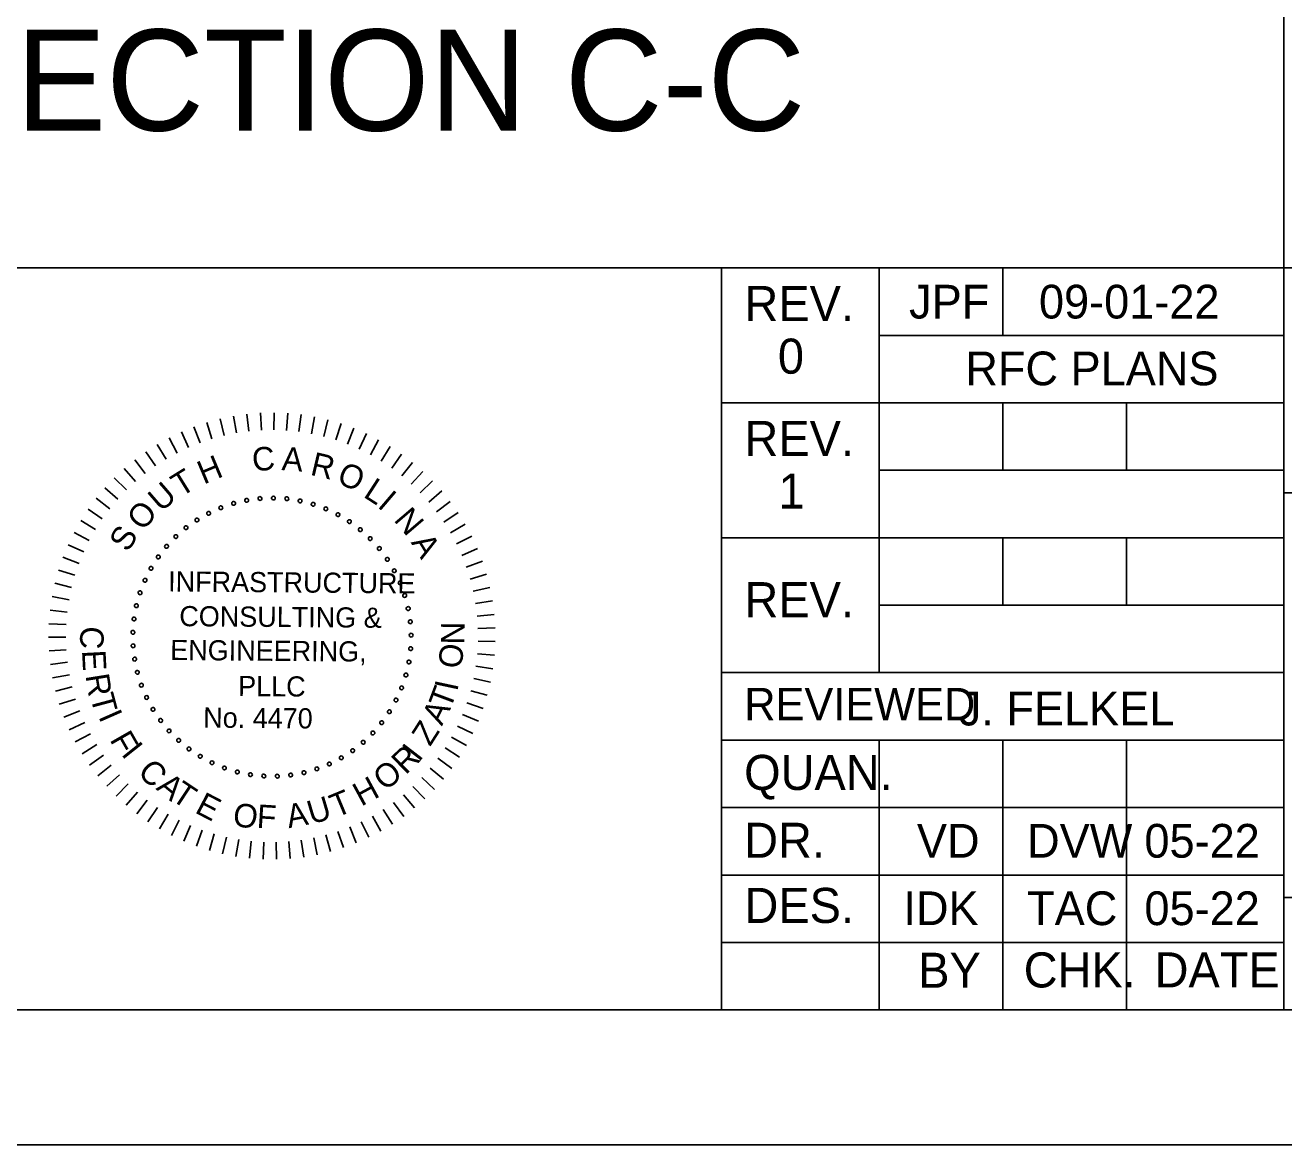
# Model space of a CAD drawing. Extents: x 1970675.2 to 1970711.3, y 796145.2 to 796167.2.
# Drawn here: x 1970700.655 to 1970705.319, y 796145.246 to 796149.396 of the extents above; entities that cross this region are included whole.
import ezdxf

# ---------------------------------------------------------------- set-up
doc = ezdxf.new("R2010")
doc.units = 0
for name, color, linetype in [('BR_BORDER LINES', 7, 'Continuous'), ('BR_TEXT', 7, 'Continuous'), ('Level 31', 7, 'Continuous')]:
    doc.layers.add(name, color=color, linetype=linetype)

msp = doc.modelspace()

# ---------------------------------------------------------------- linework, layer by layer
at = {"layer": 'BR_BORDER LINES'}
for p, q in [((1970705.3189, 796145.7463), (1970705.3189, 796151.0229)), ((1970697.8703, 796148.4964), (1970703.2355, 796148.4964)), ((1970703.2355, 796145.7463), (1970703.2355, 796148.4964)), ((1970703.2355, 796148.4964), (1970710.7358, 796148.4964)), ((1970703.8189, 796148.4964), (1970703.8189, 796146.9963)), ((1970704.2772, 796148.2464), (1970704.2772, 796148.4964)), ((1970703.8189, 796148.2464), (1970705.3189, 796148.2464)), ((1970703.2355, 796147.9964), (1970705.3189, 796147.9964)), ((1970704.2772, 796147.7464), (1970704.2772, 796147.9964)), ((1970704.7356, 796147.7464), (1970704.7356, 796147.9964)), ((1970703.8189, 796147.7464), (1970705.3189, 796147.7464)), ((1970705.3189, 796147.663), (1970705.3189, 796147.663)), ((1970705.3189, 796147.663), (1970710.736, 796147.663)), ((1970703.2355, 796147.4964), (1970705.3189, 796147.4964)), ((1970704.2772, 796147.2463), (1970704.2772, 796147.4964)), ((1970704.7356, 796147.2463), (1970704.7356, 796147.4964)), ((1970703.8189, 796147.2463), (1970705.3189, 796147.2463)), ((1970703.2355, 796146.9963), (1970705.3189, 796146.9963)), ((1970703.2355, 796146.7463), (1970705.3189, 796146.7463)), ((1970703.8189, 796146.7463), (1970703.8189, 796145.7463)), ((1970704.2772, 796146.7463), (1970704.2772, 796145.7463)), ((1970704.7356, 796146.7463), (1970704.7356, 796145.7463)), ((1970703.2355, 796146.4963), (1970705.3189, 796146.4963)), ((1970703.2355, 796146.2463), (1970705.3189, 796146.2463)), ((1970705.3189, 796146.163), (1970710.7358, 796146.163)), ((1970703.2355, 796145.9963), (1970705.3189, 796145.9963)), ((1970677.0698, 796145.7463), (1970710.7358, 796145.7463))]:
    msp.add_line(p, q, dxfattribs=at)
at = {"layer": 'BR_TEXT'}
for p, q in [((1970701.3767, 796147.9371), (1970701.3916, 796147.8752)), ((1970701.4262, 796147.9473), (1970701.4372, 796147.8846)), ((1970701.4761, 796147.9545), (1970701.4834, 796147.8913)), ((1970701.5265, 796147.9587), (1970701.5298, 796147.8951)), ((1970701.5769, 796147.9597), (1970701.5764, 796147.8961)), ((1970701.6274, 796147.9577), (1970701.623, 796147.8942)), ((1970701.6776, 796147.9526), (1970701.6693, 796147.8895)), ((1970701.7274, 796147.9445), (1970701.7153, 796147.882)), ((1970701.7767, 796147.9333), (1970701.7608, 796147.8717)), ((1970701.2334, 796147.8887), (1970701.2593, 796147.8305)), ((1970701.2802, 796147.9077), (1970701.3025, 796147.8481)), ((1970701.328, 796147.9239), (1970701.3466, 796147.863)), ((1970701.8251, 796147.9192), (1970701.8055, 796147.8586)), ((1970701.8726, 796147.9021), (1970701.8494, 796147.8428)), ((1970701.1439, 796147.8422), (1970701.1766, 796147.7876)), ((1970701.1879, 796147.8668), (1970701.2173, 796147.8103)), ((1970701.919, 796147.8822), (1970701.8922, 796147.8244)), ((1970701.9641, 796147.8594), (1970701.9338, 796147.8034)), ((1970701.1014, 796147.8149), (1970701.1374, 796147.7625)), ((1970702.0077, 796147.834), (1970701.974, 796147.78)), ((1970702.0497, 796147.8059), (1970702.0128, 796147.7541)), ((1970701.0217, 796147.7529), (1970701.0639, 796147.7052)), ((1970701.0606, 796147.7852), (1970701.0998, 796147.735)), ((1970702.0899, 796147.7754), (1970702.0499, 796147.7259)), ((1970700.9849, 796147.7184), (1970701.0299, 796147.6734)), ((1970702.1281, 796147.7424), (1970702.0852, 796147.6954)), ((1970702.1643, 796147.7072), (1970702.1186, 796147.6629)), ((1970700.9502, 796147.6817), (1970700.9979, 796147.6395)), ((1970702.1982, 796147.6699), (1970702.1499, 796147.6284)), ((1970700.9179, 796147.643), (1970700.968, 796147.6037)), ((1970702.2299, 796147.6305), (1970702.1791, 796147.5921)), ((1970700.8605, 796147.5599), (1970700.9151, 796147.5271)), ((1970700.8879, 796147.6023), (1970700.9404, 796147.5662)), ((1970702.259, 796147.5893), (1970702.206, 796147.5541)), ((1970700.8358, 796147.5159), (1970700.8922, 796147.4865)), ((1970702.2856, 796147.5464), (1970702.2305, 796147.5145)), ((1970700.8137, 796147.4705), (1970700.8719, 796147.4445)), ((1970702.3095, 796147.5019), (1970702.2526, 796147.4734)), ((1970700.7945, 796147.4238), (1970700.8541, 796147.4014)), ((1970702.3307, 796147.4561), (1970702.2722, 796147.4311)), ((1970700.7782, 796147.3761), (1970700.839, 796147.3574)), ((1970702.3491, 796147.4091), (1970702.2891, 796147.3877)), ((1970700.7648, 796147.3274), (1970700.8267, 796147.3124)), ((1970702.3645, 796147.361), (1970702.3033, 796147.3433)), ((1970702.377, 796147.3121), (1970702.3148, 796147.2982)), ((1970700.7543, 796147.278), (1970700.817, 796147.2668)), ((1970702.3864, 796147.2625), (1970702.3236, 796147.2524)), ((1970700.747, 796147.228), (1970700.8102, 796147.2207)), ((1970702.3929, 796147.2124), (1970702.3295, 796147.2062)), ((1970700.7426, 796147.1777), (1970700.8062, 796147.1743)), ((1970702.3963, 796147.1621), (1970702.3326, 796147.1597)), ((1970700.7414, 796147.1273), (1970700.8051, 796147.1277)), ((1970702.3965, 796147.1116), (1970702.3329, 796147.1131)), ((1970700.7432, 796147.0768), (1970700.8067, 796147.0812)), ((1970702.3938, 796147.0612), (1970702.3303, 796147.0666)), ((1970700.7481, 796147.0266), (1970700.8113, 796147.0348)), ((1970702.3879, 796147.011), (1970702.3249, 796147.0203)), ((1970700.7561, 796146.9767), (1970700.8186, 796146.9888)), ((1970702.379, 796146.9613), (1970702.3167, 796146.9744)), ((1970700.7671, 796146.9275), (1970700.8287, 796146.9433)), ((1970702.3671, 796146.9123), (1970702.3057, 796146.9291)), ((1970700.781, 796146.8789), (1970700.8416, 796146.8985)), ((1970702.3522, 796146.864), (1970702.2919, 796146.8846)), ((1970700.7979, 796146.8314), (1970700.8572, 796146.8546)), ((1970702.3344, 796146.8168), (1970702.2755, 796146.841)), ((1970700.8177, 796146.7849), (1970700.8755, 796146.8117)), ((1970700.8403, 796146.7397), (1970700.8963, 796146.77)), ((1970702.3138, 796146.7707), (1970702.2564, 796146.7985)), ((1970700.8655, 796146.696), (1970700.9196, 796146.7297)), ((1970702.2904, 796146.726), (1970702.2348, 796146.7572)), ((1970700.8934, 796146.654), (1970700.9453, 796146.6908)), ((1970702.2356, 796146.6412), (1970702.1843, 796146.6789)), ((1970702.2643, 796146.6828), (1970702.2107, 796146.7173)), ((1970700.9238, 796146.6137), (1970700.9734, 796146.6536)), ((1970702.2044, 796146.6015), (1970702.1555, 796146.6423)), ((1970700.9566, 796146.5753), (1970701.0037, 796146.6182)), ((1970700.9917, 796146.539), (1970701.0361, 796146.5847)), ((1970702.1709, 796146.5638), (1970702.1245, 796146.6074)), ((1970701.0289, 796146.5049), (1970701.0704, 796146.5532)), ((1970702.0973, 796146.4948), (1970702.0566, 796146.5437)), ((1970702.1351, 796146.5281), (1970702.0915, 796146.5745)), ((1970701.0682, 796146.4731), (1970701.1066, 796146.5239)), ((1970701.1093, 796146.4438), (1970701.1446, 796146.4968)), ((1970702.0158, 796146.4352), (1970701.9813, 796146.4888)), ((1970702.0574, 796146.4637), (1970702.0198, 796146.5151)), ((1970701.1521, 796146.4171), (1970701.1841, 796146.4721)), ((1970701.1965, 796146.393), (1970701.225, 796146.4499)), ((1970701.9276, 796146.386), (1970701.9, 796146.4434)), ((1970701.9725, 796146.4093), (1970701.9414, 796146.4648)), ((1970701.2422, 796146.3716), (1970701.2673, 796146.4302)), ((1970701.2892, 796146.3531), (1970701.3106, 796146.4131)), ((1970701.3372, 796146.3375), (1970701.3549, 796146.3986)), ((1970701.7859, 796146.3332), (1970701.7691, 796146.3947)), ((1970701.8342, 796146.3479), (1970701.8137, 796146.4082)), ((1970701.8815, 796146.3656), (1970701.8574, 796146.4245)), ((1970701.386, 796146.3248), (1970701.4001, 796146.3869)), ((1970701.4356, 796146.3152), (1970701.4458, 796146.378)), ((1970701.4856, 796146.3086), (1970701.492, 796146.3719)), ((1970701.536, 796146.305), (1970701.5385, 796146.3686)), ((1970701.5865, 796146.3045), (1970701.5851, 796146.3682)), ((1970701.6369, 796146.3071), (1970701.6316, 796146.3706)), ((1970701.6871, 796146.3128), (1970701.6779, 796146.3758)), ((1970701.7368, 796146.3215), (1970701.7238, 796146.3838))]:
    msp.add_line(p, q, dxfattribs=at)
for centre, start, end in [((1970701.3797, 796147.6075), 21.6807, 201.6807), ((1970701.3797, 796147.6075), 201.6807, 21.6807), ((1970701.4268, 796147.6235), 16.1422, 196.1422), ((1970701.4268, 796147.6235), 196.1422, 16.1422), ((1970701.4753, 796147.635), 10.6038, 190.6038), ((1970701.4753, 796147.635), 190.6038, 10.6038), ((1970701.5247, 796147.6417), 5.0653, 185.0653), ((1970701.5247, 796147.6417), 185.0653, 5.0653), ((1970701.5745, 796147.6436), 359.5268, 179.5268), ((1970701.5745, 796147.6436), 179.5268, 359.5268), ((1970701.6242, 796147.6407), 173.9884, 353.9884), ((1970701.6242, 796147.6407), 353.9884, 173.9884), ((1970701.6735, 796147.6329), 168.4499, 348.4499), ((1970701.6735, 796147.6329), 348.4499, 168.4499), ((1970701.7217, 796147.6205), 162.9114, 342.9114), ((1970701.7217, 796147.6205), 342.9114, 162.9114), ((1970701.7686, 796147.6035), 157.373, 337.373), ((1970701.7686, 796147.6035), 337.373, 157.373), ((1970701.291, 796147.5621), 32.7576, 212.7576), ((1970701.291, 796147.5621), 212.7576, 32.7576), ((1970701.3343, 796147.587), 27.2191, 207.2191), ((1970701.3343, 796147.587), 207.2191, 27.2191), ((1970701.8135, 796147.582), 151.8345, 331.8345), ((1970701.8135, 796147.582), 331.8345, 151.8345), ((1970701.8562, 796147.5563), 146.2961, 326.2961), ((1970701.8562, 796147.5563), 326.2961, 146.2961), ((1970701.2504, 796147.5333), 38.2961, 218.2961), ((1970701.2504, 796147.5333), 218.2961, 38.2961), ((1970701.8962, 796147.5266), 140.7576, 320.7576), ((1970701.8962, 796147.5266), 320.7576, 140.7576), ((1970701.1785, 796147.4645), 49.373, 229.373), ((1970701.1785, 796147.4645), 229.373, 49.373), ((1970701.2128, 796147.5006), 43.8345, 223.8345), ((1970701.2128, 796147.5006), 223.8345, 43.8345), ((1970701.9332, 796147.4932), 135.2191, 315.2191), ((1970701.9332, 796147.4932), 315.2191, 135.2191), ((1970701.1478, 796147.4252), 54.9114, 234.9114), ((1970701.1478, 796147.4252), 234.9114, 54.9114), ((1970701.9668, 796147.4564), 129.6807, 309.6807), ((1970701.9668, 796147.4564), 309.6807, 129.6807), ((1970701.9966, 796147.4165), 124.1422, 304.1422), ((1970701.9966, 796147.4165), 304.1422, 124.1422), ((1970701.1211, 796147.3831), 60.4499, 240.4499), ((1970701.1211, 796147.3831), 240.4499, 60.4499), ((1970702.0225, 796147.3739), 118.6038, 298.6038), ((1970702.0225, 796147.3739), 298.6038, 118.6038), ((1970701.0986, 796147.3387), 65.9884, 245.9884), ((1970701.0986, 796147.3387), 245.9884, 65.9884), ((1970702.0441, 796147.329), 113.0653, 293.0653), ((1970702.0441, 796147.329), 293.0653, 113.0653), ((1970701.0804, 796147.2923), 71.5268, 251.5268), ((1970701.0804, 796147.2923), 251.5268, 71.5268), ((1970702.0613, 796147.2822), 107.5268, 287.5268), ((1970702.0613, 796147.2822), 287.5268, 107.5268), ((1970701.0668, 796147.2443), 77.0653, 257.0653), ((1970701.0668, 796147.2443), 257.0653, 77.0653), ((1970702.0739, 796147.234), 101.9884, 281.9884), ((1970702.0739, 796147.234), 281.9884, 101.9884), ((1970701.0579, 796147.1953), 82.6038, 262.6038), ((1970701.0579, 796147.1953), 262.6038, 82.6038), ((1970702.0818, 796147.1848), 96.4499, 276.4499), ((1970702.0818, 796147.1848), 276.4499, 96.4499), ((1970701.0538, 796147.1456), 88.1422, 268.1422), ((1970701.0538, 796147.1456), 268.1422, 88.1422), ((1970702.0849, 796147.1351), 90.9114, 270.9114), ((1970702.0849, 796147.1351), 270.9114, 90.9114), ((1970701.0545, 796147.0958), 93.6807, 273.6807), ((1970701.0545, 796147.0958), 273.6807, 93.6807), ((1970701.06, 796147.0463), 99.2191, 279.2191), ((1970701.06, 796147.0463), 279.2191, 99.2191), ((1970702.0832, 796147.0853), 85.373, 265.373), ((1970702.0832, 796147.0853), 265.373, 85.373), ((1970701.0703, 796146.9975), 104.7576, 284.7576), ((1970701.0703, 796146.9975), 284.7576, 104.7576), ((1970702.0766, 796147.0359), 79.8345, 259.8345), ((1970702.0766, 796147.0359), 259.8345, 79.8345), ((1970701.0852, 796146.95), 110.2961, 290.2961), ((1970701.0852, 796146.95), 290.2961, 110.2961), ((1970702.0654, 796146.9873), 74.2961, 254.2961), ((1970702.0654, 796146.9873), 254.2961, 74.2961), ((1970701.1046, 796146.9041), 115.8345, 295.8345), ((1970701.1046, 796146.9041), 295.8345, 115.8345), ((1970702.0495, 796146.9401), 68.7576, 248.7576), ((1970702.0495, 796146.9401), 248.7576, 68.7576), ((1970701.1284, 796146.8603), 121.373, 301.373), ((1970701.1284, 796146.8603), 301.373, 121.373), ((1970702.0291, 796146.8946), 63.2191, 243.2191), ((1970702.0291, 796146.8946), 243.2191, 63.2191), ((1970701.1563, 796146.819), 126.9114, 306.9114), ((1970701.1563, 796146.819), 306.9114, 126.9114), ((1970701.9758, 796146.8106), 52.1422, 232.1422), ((1970701.9758, 796146.8106), 232.1422, 52.1422), ((1970702.0045, 796146.8513), 57.6807, 237.6807), ((1970702.0045, 796146.8513), 237.6807, 57.6807), ((1970701.188, 796146.7806), 132.4499, 312.4499), ((1970701.188, 796146.7806), 312.4499, 132.4499), ((1970701.9432, 796146.7728), 46.6038, 226.6038), ((1970701.9432, 796146.7728), 226.6038, 46.6038), ((1970701.2233, 796146.7454), 137.9884, 317.9884), ((1970701.2233, 796146.7454), 317.9884, 137.9884), ((1970701.2618, 796146.7138), 323.5268, 143.5268), ((1970701.9072, 796146.7384), 41.0653, 221.0653), ((1970701.9072, 796146.7384), 221.0653, 41.0653), ((1970701.2618, 796146.7138), 143.5268, 323.5268), ((1970701.3032, 796146.6861), 149.0653, 329.0653), ((1970701.3032, 796146.6861), 329.0653, 149.0653), ((1970701.8261, 796146.6807), 29.9884, 209.9884), ((1970701.8261, 796146.6807), 209.9884, 29.9884), ((1970701.8681, 796146.7076), 35.5268, 215.5268), ((1970701.8681, 796146.7076), 215.5268, 35.5268), ((1970701.3471, 796146.6625), 154.6038, 334.6038), ((1970701.3471, 796146.6625), 334.6038, 154.6038), ((1970701.3931, 796146.6432), 160.1422, 340.1422), ((1970701.3931, 796146.6432), 340.1422, 160.1422), ((1970701.4407, 796146.6285), 165.6807, 345.6807), ((1970701.4407, 796146.6285), 345.6807, 165.6807), ((1970701.6875, 796146.6259), 13.373, 193.373), ((1970701.6875, 796146.6259), 193.373, 13.373), ((1970701.7354, 796146.6397), 18.9114, 198.9114), ((1970701.7354, 796146.6397), 198.9114, 18.9114), ((1970701.7817, 796146.658), 24.4499, 204.4499), ((1970701.7817, 796146.658), 204.4499, 24.4499), ((1970701.4895, 796146.6184), 171.2191, 351.2191), ((1970701.4895, 796146.6184), 351.2191, 171.2191), ((1970701.539, 796146.6131), 356.7576, 176.7576), ((1970701.539, 796146.6131), 176.7576, 356.7576), ((1970701.5889, 796146.6126), 2.2961, 182.2961), ((1970701.5889, 796146.6126), 182.2961, 2.2961), ((1970701.6385, 796146.6169), 7.8345, 187.8345), ((1970701.6385, 796146.6169), 187.8345, 7.8345)]:
    msp.add_arc(centre, 0.00701, start, end, dxfattribs=at)
at = {"layer": 'Level 31'}
msp.add_lwpolyline([(1970675.2365, 796145.2464), (1970711.2364, 796145.2464), (1970711.2364, 796167.2463), (1970675.2365, 796167.2463)], close=True, dxfattribs=at)

# ---------------------------------------------------------------- texts
at = {"layer": 'BR_TEXT'}
for s, height, rotation, p in [('SECTION C-C', 0.375005, 360, (1970700.286, 796149.0049)), ('H', 0.0872, 22.7882, (1970701.3162, 796147.6927)), ('C', 0.0872, 4.7281, (1970701.499, 796147.7421)), ('A', 0.0872, 355.6981, (1970701.6035, 796147.7471)), ('R', 0.0872, 346.6681, (1970701.7077, 796147.7301)), ('T', 0.0872, 31.8182, (1970701.2313, 796147.6451)), ('O', 0.0872, 337.638, (1970701.8055, 796147.7003)), ('U', 0.0872, 40.8482, (1970701.158, 796147.589)), ('L', 0.0872, 327.108, (1970701.9043, 796147.6498)), ('I', 0.0872, 319.578, (1970701.9569, 796147.612)), ('O', 0.0872, 49.8782, (1970701.091, 796147.518)), ('N', 0.0872, 310.548, (1970702.0177, 796147.5612)), ('S', 0.0872, 58.9083, (1970701.0356, 796147.4398)), ('A', 0.0872, 301.5179, (1970702.0828, 796147.4788)), ('INFRASTRUCTURE', 0.074771, 359.5268, (1970701.1842, 796147.2972)), ('CONSULTING &', 0.074771, 359.5268, (1970701.2255, 796147.1686)), ('C', 0.0872, 267.025, (1970700.8606, 796147.1698)), ('N', 0.0872, 89.2085, (1970702.2821, 796147.1001)), ('ENGINEERING,', 0.074771, 359.5268, (1970701.1919, 796147.0432)), ('O', 0.0872, 83.2085, (1970702.271, 796147.0086)), ('E', 0.0872, 273.025, (1970700.865, 796147.0783)), ('R', 0.0872, 279.025, (1970700.8778, 796146.986)), ('PLLC', 0.07477, 359.5268, (1970701.4436, 796146.9096)), ('I', 0.0872, 77.9093, (1970702.2555, 796146.9243)), ('T', 0.0872, 285.025, (1970700.8952, 796146.9072)), ('T', 0.0872, 69.3954, (1970702.2298, 796146.8568)), ('I', 0.0872, 293.7713, (1970700.9249, 796146.8341)), ('No. 4470', 0.07477, 359.5268, (1970701.3141, 796146.7927)), ('A', 0.0872, 63.3954, (1970702.199, 796146.7965)), ('Z', 0.0872, 57.3954, (1970702.1551, 796146.7202)), ('F', 0.0872, 299.7713, (1970700.9661, 796146.748)), ('I', 0.0872, 308.5268, (1970701.0082, 796146.6942)), ('R', 0.0872, 44.5268, (1970702.0647, 796146.6152)), ('I', 0.0872, 52.3339, (1970702.1141, 796146.6625)), ('C', 0.0872, 314.5268, (1970701.0675, 796146.6241)), ('O', 0.0872, 38.5268, (1970701.9881, 796146.5552)), ('A', 0.0872, 320.5268, (1970701.1367, 796146.5655)), ('T', 0.0872, 326.5268, (1970701.1911, 796146.527)), ('H', 0.0872, 28.5268, (1970701.9, 796146.4992)), ('E', 0.0872, 332.5268, (1970701.2797, 796146.4792)), ('U', 0.0872, 16.5268, (1970701.7151, 796146.4331)), ('T', 0.0872, 22.5268, (1970701.8068, 796146.4575)), ('O', 0.0872, 350.5268, (1970701.4198, 796146.4304)), ('F', 0.0872, 356.5268, (1970701.5113, 796146.4212)), ('A', 0.0872, 10.5268, (1970701.6312, 796146.4196))]:
    msp.add_text(s, height=height, rotation=rotation, dxfattribs=at).set_placement(p)
for s, height, p in [('REV.', 0.13001, (1970703.3202, 796148.2993)), ('JPF', 0.12499, (1970703.9304, 796148.3088)), ('09-01-22', 0.12499, (1970704.4116, 796148.3088)), ('0', 0.13, (1970703.4441, 796148.1043)), ('RFC PLANS', 0.12499, (1970704.1388, 796148.0613)), ('REV.', 0.13001, (1970703.3202, 796147.7993)), ('1', 0.13, (1970703.4461, 796147.6043)), ('REV.', 0.13001, (1970703.3202, 796147.2018)), ('REVIEWED', 0.12, (1970703.3195, 796146.8198)), ('J. FELKEL', 0.12499, (1970704.1145, 796146.8007)), ('QUAN.', 0.13001, (1970703.3189, 796146.5615)), ('DR.', 0.13001, (1970703.3191, 796146.31)), ('VD', 0.12499, (1970703.9593, 796146.3106)), ('DVW', 0.12499, (1970704.3677, 796146.3106)), ('05-22', 0.12499, (1970704.8024, 796146.3106)), ('DES.', 0.13001, (1970703.3202, 796146.0686)), ('IDK', 0.12499, (1970703.9093, 796146.0606)), ('TAC', 0.12499, (1970704.3677, 796146.0606)), ('05-22', 0.12499, (1970704.8024, 796146.0606)), ('BY', 0.13001, (1970703.9642, 796145.8283)), ('CHK.', 0.13001, (1970704.355, 796145.8296)), ('DATE', 0.13001, (1970704.8402, 796145.8297))]:
    msp.add_text(s, height=height, dxfattribs=at).set_placement(p)

doc.saveas('drawing.dxf')
